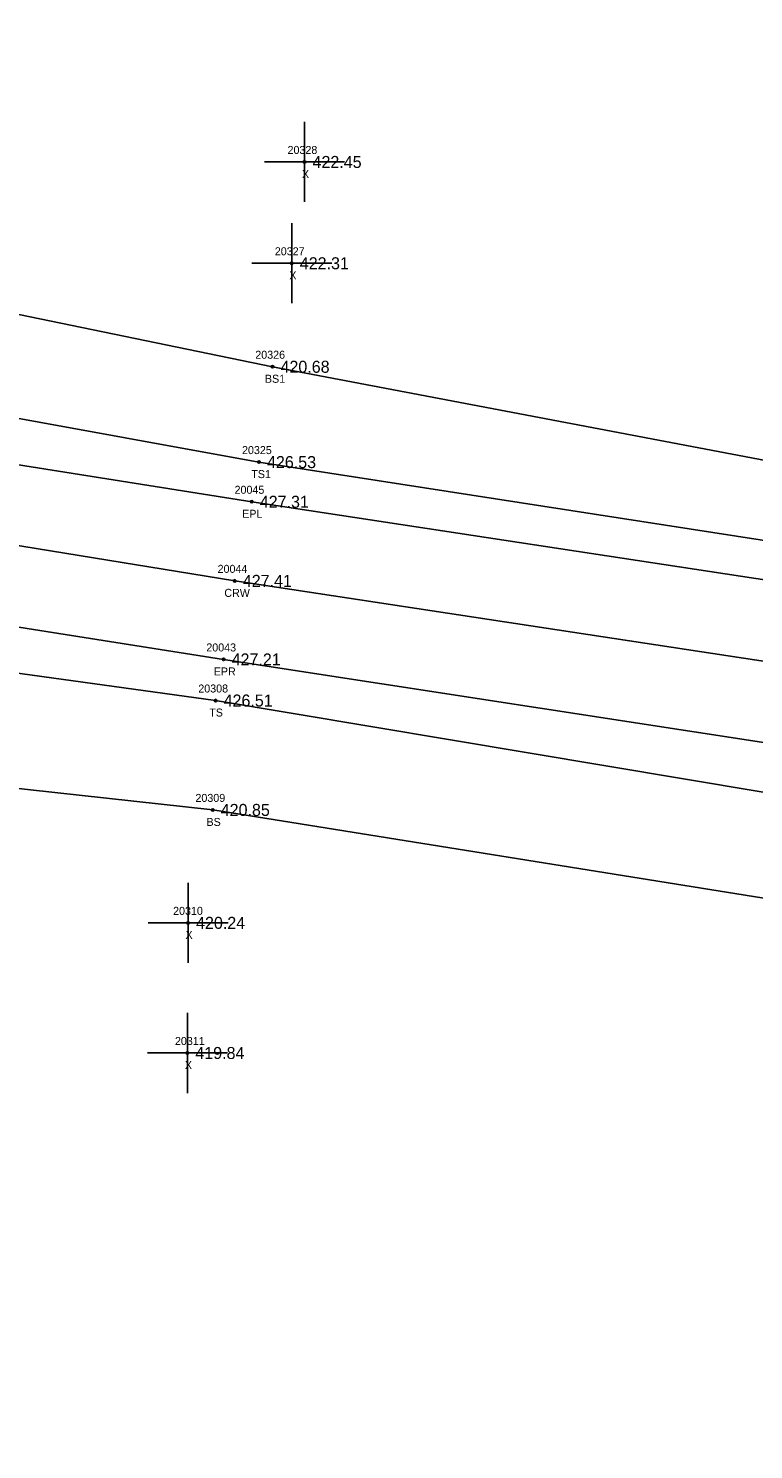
# Model space of a CAD drawing. Extents: x 1613184 to 1614731, y 770859 to 771868.
# Drawn here: x 1614138.1 to 1614228.7, y 771198.3 to 771375.9 of the extents above; entities that cross this region are included whole.
import ezdxf

# ---------------------------------------------------------------- set-up
doc = ezdxf.new("R2010")
doc.units = 0
for name, color, linetype in [('RD_DTM_BkLn1', 7, 'Continuous'), ('RD_DTM_BkLn2', 7, 'Continuous'), ('RD_DTM_BkLn_txCode', 7, 'Continuous'), ('RD_EX_Misc', 7, 'Continuous'), ('RD_EX_Misc_txCode', 7, 'Continuous'), ('RD_EX_Road', 7, 'Continuous'), ('RD_EX_Road_txCode', 7, 'Continuous'), ('RD_EX_TX_Misc_ELEV', 7, 'Continuous'), ('RD_EX_TX_Road_ELEV', 7, 'Continuous'), ('RD_HC_Survey_ELEV', 7, 'Continuous'), ('RD_HC_Survey_txCode', 7, 'Continuous'), ('RD_SMD_Locator', 7, 'Continuous')]:
    doc.layers.add(name, color=color, linetype=linetype)

msp = doc.modelspace()

# ---------------------------------------------------------------- linework, layer by layer
at = {"layer": 'RD_DTM_BkLn1'}
msp.add_lwpolyline([(1613965.11, 771336.88), (1614064.55, 771323.02), (1614163.88, 771306.86), (1614262.51, 771291.89), (1614361.57, 771275.2), (1614461.76, 771258.77), (1614560.71, 771243.49), (1614660.13, 771228.22)], dxfattribs=at)
at = {"layer": 'RD_DTM_BkLn2'}
for points in [[(1613936.71, 771369.76), (1613950.83, 771373.56), (1613963.82, 771375.88), (1614069.43, 771354.05), (1614168.59, 771333.61), (1614242.69, 771319.53), (1614249.02, 771318.73)], [(1613967.95, 771351.3), (1613989.67, 771350.48), (1614067.09, 771339.84), (1614166.9, 771321.7), (1614241.35, 771310.16), (1614249.01, 771310.92), (1614252.45, 771315.33), (1614253.58, 771323.09), (1614240.02, 771322.23)], [(1613964.19, 771322.73), (1613968.82, 771317.98), (1613995.59, 771312.64), (1614063.18, 771305.5), (1614161.48, 771291.91), (1614259.01, 771275.6), (1614358.23, 771261.08), (1614459.56, 771246.25), (1614559.08, 771230.48), (1614643.28, 771216.31), (1614658.67, 771214.41)], [(1613942.37, 771316.04), (1613958.6, 771307.1), (1613993.85, 771297.11), (1614061.98, 771289.14), (1614161.12, 771278.24), (1614255.97, 771263.05), (1614304.44, 771258.76), (1614327.58, 771260.25), (1614357.86, 771257.94), (1614459.3, 771244.57), (1614558.63, 771228.44), (1614632.25, 771215.15), (1614636.04, 771209.87), (1614639.16, 771208.8), (1614642.36, 771211.01), (1614643.75, 771203.68), (1614650.35, 771198.32), (1614658.52, 771198.65)]]:
    msp.add_lwpolyline(points, dxfattribs=at)
at = {"layer": 'RD_EX_Misc'}
for p, q in [((1614172.59, 771354.2), (1614172.59, 771364.2)), ((1614167.59, 771359.2), (1614177.59, 771359.2)), ((1614171, 771341.54), (1614171, 771351.54)), ((1614166, 771346.54), (1614176, 771346.54)), ((1614158.04, 771259.13), (1614158.04, 771269.13)), ((1614153.04, 771264.13), (1614163.04, 771264.13)), ((1614157.95, 771242.87), (1614157.95, 771252.87)), ((1614152.95, 771247.87), (1614162.95, 771247.87))]:
    msp.add_line(p, q, dxfattribs=at)
at = {"layer": 'RD_EX_Road'}
for points in [[(1613966.21, 771346.72), (1614065.91, 771332.61), (1614166, 771316.74), (1614252.8, 771303.53), (1614264.27, 771301.76), (1614271.95, 771300.8), (1614363.43, 771285.99), (1614463.49, 771269.68), (1614562.24, 771253.72), (1614661.91, 771238.32)], [(1613963.41, 771324.71), (1614062.98, 771312.73), (1614162.48, 771297.04), (1614260.87, 771281.9), (1614360.23, 771265.95), (1614460.24, 771249.77), (1614559.17, 771233.87), (1614658.84, 771218.34)]]:
    msp.add_lwpolyline(points, dxfattribs=at)
at = {"layer": 'RD_SMD_Locator'}
for centre in [(1614172.59, 771359.2), (1614171, 771346.54), (1614168.59, 771333.61), (1614166.9, 771321.7), (1614166, 771316.74), (1614163.88, 771306.86), (1614162.48, 771297.04), (1614161.48, 771291.91), (1614161.12, 771278.24), (1614158.04, 771264.13), (1614157.95, 771247.87)]:
    msp.add_circle(centre, 0.15, dxfattribs=at)

# ---------------------------------------------------------------- texts
at = {"layer": 'RD_DTM_BkLn_txCode'}
for s, p in [('20326', (1614166.44, 771334.61)), ('BS1', (1614167.64, 771331.61)), ('20325', (1614164.78, 771322.7)), ('TS1', (1614165.94, 771319.7)), ('20308', (1614159.32, 771292.91)), ('TS', (1614160.69, 771289.91)), ('20309', (1614158.96, 771279.24)), ('BS', (1614160.34, 771276.24))]:
    msp.add_text(s, height=1, dxfattribs=at).set_placement(p)
at = {"layer": 'RD_EX_Misc_txCode'}
for s, p in [('20328', (1614170.47, 771360.2)), ('X', (1614172.27, 771357.2)), ('20327', (1614168.88, 771347.54)), ('X', (1614170.69, 771344.54)), ('20310', (1614156.17, 771265.13)), ('X', (1614157.72, 771262.13)), ('20311', (1614156.4, 771248.87)), ('X', (1614157.64, 771245.87))]:
    msp.add_text(s, height=1, dxfattribs=at).set_placement(p)
at = {"layer": 'RD_EX_Road_txCode'}
for s, p in [('20045', (1614163.85, 771317.74)), ('EPL', (1614164.8, 771314.74)), ('20043', (1614160.32, 771298.04)), ('EPR', (1614161.25, 771295.04))]:
    msp.add_text(s, height=1, dxfattribs=at).set_placement(p)
at = {"layer": 'RD_EX_TX_Misc_ELEV'}
for s, p in [('422.45', (1614173.59, 771358.45)), ('422.31', (1614172, 771345.79)), ('420.68', (1614169.59, 771332.86)), ('426.53', (1614167.9, 771320.95)), ('426.51', (1614162.48, 771291.16)), ('420.85', (1614162.12, 771277.49)), ('420.24', (1614159.04, 771263.38)), ('419.84', (1614158.95, 771247.12))]:
    msp.add_text(s, height=1.5, dxfattribs=at).set_placement(p)
at = {"layer": 'RD_EX_TX_Road_ELEV'}
for s, p in [('427.31', (1614167, 771315.99)), ('427.21', (1614163.48, 771296.29))]:
    msp.add_text(s, height=1.5, dxfattribs=at).set_placement(p)
at = {"layer": 'RD_HC_Survey_ELEV'}
msp.add_text('427.41', height=1.5, dxfattribs=at).set_placement((1614164.88, 771306.11))
at = {"layer": 'RD_HC_Survey_txCode'}
for s, p in [('20044', (1614161.73, 771307.86)), ('CRW', (1614162.57, 771304.86))]:
    msp.add_text(s, height=1, dxfattribs=at).set_placement(p)

doc.saveas('drawing.dxf')
